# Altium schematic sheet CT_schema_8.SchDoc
size 274 x 160 mm
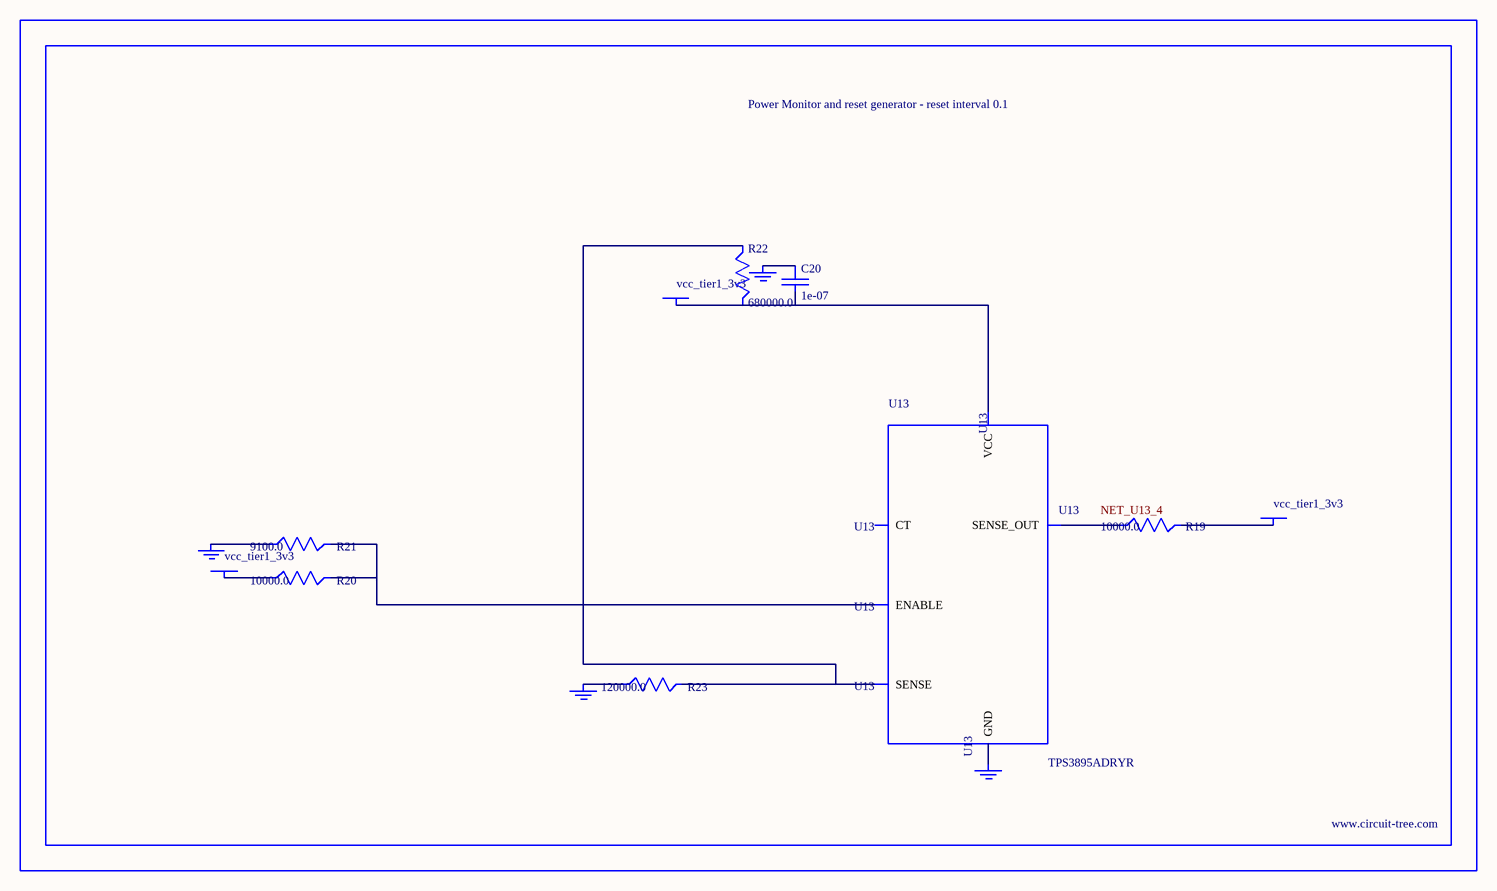
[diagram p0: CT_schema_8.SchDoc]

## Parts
BORDER7  (no value)
C20  1e-07  [C0402]
GND_INSTANCE_7_0  (no value)
GND_INSTANCE_7_1  (no value)
GND_INSTANCE_7_2  (no value)
GND_INSTANCE_7_3  (no value)
POWER_INSTANCE_7_0  vcc_tier1_3v3
POWER_INSTANCE_7_1  vcc_tier1_3v3
POWER_INSTANCE_7_2  vcc_tier1_3v3
R19  10000.0  [R0603]
R20  10000.0  [R0603]
R21  9100.0  [R0603]
R22  680000.0  [R0603]
R23  120000.0  [R0603]
U13  TPS3895ADRYR  [SON-6]

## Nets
NetC20_1: C20.1 GND_INSTANCE_7_2.0(GND)
NetC20_2: C20.2 POWER_INSTANCE_7_2.0(PWR) R22.2 U13.6(VCC)
NetGND_INSTANCE_7_0_0: GND_INSTANCE_7_0.0(GND) R21.1
NetGND_INSTANCE_7_1_0: GND_INSTANCE_7_1.0(GND) R23.1
NetGND_INSTANCE_7_3_0: GND_INSTANCE_7_3.0(GND) U13.2(GND)
NetPOWER_INSTANCE_7_0_0: POWER_INSTANCE_7_0.0(PWR) R20.1
NetPOWER_INSTANCE_7_1_0: POWER_INSTANCE_7_1.0(PWR) R19.2
NetR19_1: R19.1 U13.4(SENSE_OUT)
NetR20_2: R20.2 R21.2 U13.1(ENABLE)
NetR22_1: R22.1 R23.2 U13.3(SENSE)

Not connected (* = marked no-connect by the designer): U13 5(CT)

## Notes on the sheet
- Labels drawn without touching a wire or pin: NET_U13_4

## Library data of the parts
BORDER7 = BORDER_PAGE7
C20 = C0402C104K3RACTU
GND_INSTANCE_7_0-GND_INSTANCE_7_3 = GND
POWER_INSTANCE_7_0-POWER_INSTANCE_7_2 = PWR
R19 R20 = RC0603JR-0710KL
R21 = RC0603JR-079K1L
R22 = RC0603JR-07680KL
R23 = RC0603JR-07120KL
